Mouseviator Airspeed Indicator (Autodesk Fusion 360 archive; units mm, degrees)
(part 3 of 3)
sketch "Sketch2" plane through (-9, 0, 0) normal (-1, 0, 0) x axis (0, 0, 1)
  line L1 (17.6759, -7.8551) -> (17.6759, -8.2743)
  line L2 (17.6759, 6.5541) -> (17.6759, 6.1349)
  line L3 (15.1488, 7.9637) -> (16.0708, 8.8862)
  line L4 (13.2614, 9.6883) -> (14.9498, 8.0007)
  line L5 (14.1646, 10.7942) -> (13.274, 9.873)
  line L6 (11.3861, 12.4172) -> (11.8062, 12.4172)
  line L7 (-2.9837, 12.4223) -> (-2.5631, 12.4223)
  line L8 (-8.873, 6.1148) -> (-8.873, 6.5351)
  line L9 (-8.873, -8.2553) -> (-8.873, -7.835)
  line L10 (-2.5727, -14.1374) -> (-2.9927, -14.1374)
  line L11 (11.8062, -14.1374) -> (11.3861, -14.1374)
  circle C1 centre (4.4067, -14.3661) radius 0.9326
  circle C2 centre (4.4067, 12.6425) radius 0.9209
  arc A1 centre (20.4506, -5.5922) radius 9.3615 clockwise from (14.1561, -12.5216) to (13.2578, -11.584)
  arc A2 centre (13.4029, -11.5164) radius 0.16 clockwise from (13.2578, -11.584) to (13.2817, -11.4119)
  arc A3 centre (46.5076, -42.5964) radius 45.5679 clockwise from (13.2817, -11.4119) to (14.9454, -9.7291)
  arc A4 centre (15.0489, -9.8031) radius 0.1272 clockwise from (14.9454, -9.7291) to (15.1488, -9.7243)
  arc A5 centre (5.0124, -21.2003) radius 15.3116 clockwise from (15.1488, -9.7243) to (16.0692, -10.6082)
  arc A6 centre (4.4067, -0.8601) radius 15.2 clockwise from (17.6759, -8.2743) to (16.0692, -10.6082)
  arc A7 centre (4.4067, -0.8601) radius 15 clockwise from (17.6759, 6.1349) to (17.6759, -7.8551)
  arc A8 centre (4.4067, -0.8601) radius 15.2 clockwise from (16.0708, 8.8862) to (17.6759, 6.5541)
  arc A9 centre (15.0762, 8.1271) radius 0.1788 clockwise from (15.1488, 7.9637) to (14.9498, 8.0007)
  arc A10 centre (13.3772, 9.7732) radius 0.1436 clockwise from (13.2614, 9.6883) to (13.274, 9.873)
  arc A11 centre (4.4067, -0.8601) radius 15.2 clockwise from (11.8062, 12.4172) to (14.1646, 10.7942)
  arc A12 centre (4.4067, -0.8601) radius 15 clockwise from (6.3118, 14.0184) to (11.3861, 12.4172)
  arc A13 centre (4.4067, 12.6425) radius 2.35 clockwise from (2.5017, 14.0184) to (6.3118, 14.0184)
  arc A14 centre (4.4067, -0.8601) radius 15 clockwise from (-2.5631, 12.4223) to (2.5017, 14.0184)
  arc A15 centre (4.4067, -0.8601) radius 15.2 clockwise from (-5.3368, 10.8063) to (-2.9837, 12.4223)
  arc A16 centre (-27.3451, -12.2651) radius 31.885 clockwise from (-5.3368, 10.8063) to (-4.4145, 9.8899)
  arc A17 centre (-4.4478, 9.7984) radius 0.0973 clockwise from (-4.4145, 9.8899) to (-4.4326, 9.7023)
  arc A18 centre (158.4507, -154.9056) radius 231.5744 clockwise from (-6.1572, 7.9777) to (-4.4326, 9.7023)
  arc A19 centre (-6.2246, 8.0786) radius 0.1214 clockwise from (-6.1572, 7.9777) to (-6.3071, 7.9895)
  arc A20 centre (0.3735, 15.8934) radius 10.349 clockwise from (-6.3071, 7.9895) to (-7.2502, 8.8947)
  arc A21 centre (4.4067, -0.8601) radius 15.2 clockwise from (-8.873, 6.5351) to (-7.2502, 8.8947)
  arc A22 centre (4.4067, -0.8601) radius 15 clockwise from (-8.873, -7.835) to (-8.873, 6.1148)
  arc A23 centre (4.4067, -0.8601) radius 15.2 clockwise from (-7.2537, -10.6107) to (-8.873, -8.2553)
  arc A24 centre (39.755, -59.3372) radius 67.706 clockwise from (-7.2537, -10.6107) to (-6.3203, -9.7271)
  arc A25 centre (-6.2457, -9.8075) radius 0.1097 clockwise from (-6.3203, -9.7271) to (-6.1786, -9.7208)
  arc A26 centre (-37.8756, -43.7201) radius 46.4828 clockwise from (-6.1786, -9.7208) to (-4.4513, -11.4172)
  arc A27 centre (-4.5901, -11.5514) radius 0.193 clockwise from (-4.4513, -11.4172) to (-4.4051, -11.6064)
  arc A28 centre (-93.0217, 77.7849) radius 125.8718 clockwise from (-4.4051, -11.6064) to (-5.3401, -12.5237)
  arc A29 centre (4.4067, -0.8601) radius 15.2 clockwise from (-2.9927, -14.1374) to (-5.3401, -12.5237)
  arc A30 centre (4.4067, -0.8601) radius 15 clockwise from (2.4989, -15.7383) to (-2.5727, -14.1374)
  arc A31 centre (4.4067, -14.3661) radius 2.35 clockwise from (6.3145, -15.7383) to (2.4989, -15.7383)
  arc A32 centre (4.4067, -0.8601) radius 15 clockwise from (11.3861, -14.1374) to (6.3145, -15.7383)
  arc A33 centre (4.4067, -0.8601) radius 15.2 clockwise from (14.1561, -12.5216) to (11.8062, -14.1374)
  arc A34 centre (-26.4034, -0.8798) radius 26.136 clockwise from (-1.0345, 5.4058) to (-1.0377, -7.1782)
  arc A35 centre (-0.1196, 5.6325) radius 0.9426 clockwise from (-1.0345, 5.4058) to (-0.0026, 6.5678)
  arc A36 centre (4.422, 47.5969) radius 41.267 clockwise from (8.8766, 6.5711) to (-0.0026, 6.5678)
  arc A37 centre (8.9782, 5.6352) radius 0.9413 clockwise from (8.8766, 6.5711) to (9.8912, 5.4058)
  arc A38 centre (34.9402, -0.888) radius 25.8276 clockwise from (9.8883, -7.1704) to (9.8912, 5.4058)
  arc A39 centre (8.9696, -7.4008) radius 0.9472 clockwise from (9.8883, -7.1704) to (8.8766, -8.3434)
  arc A40 centre (4.4407, -53.3263) radius 45.2011 clockwise from (-0.0175, -8.3456) to (8.8766, -8.3434)
  arc A41 centre (-0.1204, -7.406) radius 0.9452 clockwise from (-0.0175, -8.3456) to (-1.0377, -7.1782)
  arc A42 centre (-26.528, -0.9077) radius 24.6493 clockwise from (-3.0078, 6.467) to (-2.997, -8.248)
  arc A43 centre (-3.9071, 6.2045) radius 0.9369 clockwise from (-3.7182, 7.1221) to (-3.0078, 6.467)
  arc A44 centre (6.7761, 58.1143) radius 52.0609 clockwise from (-3.7182, 7.1221) to (-4.7329, 7.3415)
  arc A45 centre (-4.5799, 8.1251) radius 0.7984 clockwise from (-4.7329, 7.3415) to (-4.4077, 8.9046)
  arc A46 centre (4.4829, 51.1212) radius 43.1426 clockwise from (12.6671, 8.762) to (-4.4077, 8.9046)
  arc A47 centre (4.7913, 50.3763) radius 43.9488 clockwise from (13.0119, 7.2031) to (12.5964, 7.1261)
  arc A48 centre (12.7605, 6.2172) radius 0.9236 clockwise from (11.8575, 6.4115) to (12.5964, 7.1261)
  arc A49 centre (34.8824, -0.9362) radius 24.1688 clockwise from (11.8459, -8.2474) to (11.8575, 6.4115)
  arc A50 centre (12.7102, -7.9921) radius 0.9012 clockwise from (12.5964, -8.8861) to (11.8459, -8.2474)
  arc A51 centre (11.8848, -14.4786) radius 5.6376 clockwise from (12.5964, -8.8861) to (13.6034, -9.1093)
  arc A52 centre (13.4359, -9.8881) radius 0.7966 clockwise from (13.6034, -9.1093) to (13.2657, -10.6663)
  arc A53 centre (4.447, -50.9752) radius 41.2623 clockwise from (-4.387, -10.6697) to (13.2657, -10.6663)
  arc A54 centre (-4.5581, -9.8892) radius 0.799 clockwise from (-4.387, -10.6697) to (-4.723, -9.1073)
  arc A55 centre (-3.467, -12.5196) radius 3.6361 clockwise from (-4.723, -9.1073) to (-3.7296, -8.893)
  arc A56 centre (-3.7878, -8.0884) radius 0.8068 clockwise from (-2.997, -8.248) to (-3.7296, -8.893)
  circle C3 centre (13.4276, 8.1127) radius 1
  circle C4 centre (13.4276, 8.1127) radius 0.6875
  circle C5 centre (4.4067, 12.6425) radius 2.25
  circle C6 centre (4.4067, -14.3661) radius 2.25
  circle C7 centre (4.4067, -14.3661) radius 1.25
  circle C8 centre (4.4067, 12.6425) radius 1.25
  circle C9 centre (0.6086, 10.5315) radius 1.5
  circle C10 centre (0.6086, 10.5315) radius 0.9
  circle C11 centre (8.2306, 10.5315) radius 1.5
  circle C12 centre (8.2306, 10.5315) radius 0.9
  circle C13 centre (0.6086, -12.3285) radius 1.5
  circle C14 centre (0.6086, -12.3285) radius 0.9
  circle C15 centre (8.2306, -12.3285) radius 1.5
  circle C16 centre (8.2306, -12.3285) radius 0.9
  circle C17 centre (-8.0934, -5.8938) radius 0.75
  circle C18 centre (16.9066, -5.8938) radius 0.75
  circle C19 centre (-8.0934, 4.1062) radius 0.75
  circle C20 centre (16.9066, 4.1062) radius 0.75
  circle C21 centre (-8.0934, -5.8938) radius 0.25
  circle C22 centre (16.9066, -5.8938) radius 0.25
  circle C23 centre (-8.0934, 4.1062) radius 0.25
  circle C24 centre (16.9066, 4.1062) radius 0.25
  circle C25 centre (-5.5763, -0.8796) radius 2
  circle C26 centre (-5.5763, -0.8796) radius 1.5
  circle C27 centre (0.6086, 10.5315) radius 0.25
  circle C28 centre (8.2286, 10.5315) radius 0.25
  circle C29 centre (0.6086, -12.3285) radius 0.25
  circle C30 centre (8.2286, -12.3285) radius 0.25
  point P113 (13.0119, 7.2031)
  point P114 (12.6671, 8.762)
  tangent A34 A35
  tangent A36 A37
  tangent A37 A38
  tangent A38 A39
  tangent A39 A40
  tangent A34 A41
  tangent A43 A44
  tangent A46 A47
  tangent A47 A48
  tangent A50 A51
  tangent A52 A53
  tangent A53 A54
  tangent A55 A56
  concentric C3 C4
  coincident C3 P113
  coincident C3 P114
  concentric C2 C5
  concentric C1 C6
  concentric C6 C7
  concentric C5 C8
  concentric C9 C10
  concentric C17 C21
  concentric C25 C26
  concentric C10 C27
  dimension "d41" diameter C3 = 2
  dimension "d42" diameter C4 = 1.375
  dimension "d47" diameter C5 = 4.5
  dimension "d48" diameter C6 = 4.5
  dimension "d49" diameter C7 = 2.5
  dimension "d50" diameter C8 = 2.5
  dimension "d51" diameter C9 = 3
  dimension "d52" diameter C10 = 1.8
  dimension "d57" diameter C17 = 1.5
  dimension "d62" diameter C21 = 0.5
  dimension "d67" diameter C25 = 4
  dimension "d68" diameter C26 = 3
  dimension "d73" diameter C27 = 0.5
  dimension "d55" R-Pattern1-uDistance = 7.622
  dimension "d56" R-Pattern1-vDistance = -22.86
  dimension "d60" R-Pattern2-uDistance = 25
  dimension "d61" R-Pattern2-vDistance = 10
  dimension "d65" R-Pattern3-uDistance = 25
  dimension "d66" R-Pattern3-vDistance = 10
  dimension "d76" R-Pattern4-uDistance = 7.62
  dimension "d77" R-Pattern4-vDistance = -22.86
extrude "Extrude12" add sketch "Sketch2" profile of A34 A35 A36 A37 A38 A39 A40 A41 A42 A43 A44 A45 A46 A47 A48 A49 A50 A51 A52 A53 A54 A55 A56 C3 along normal blind 0.3
extrude "Extrude13" add sketch "Sketch2" profile of L4 C3 C4 along normal blind 4.7
extrude "Extrude14" add sketch "Sketch2" profile of C25 C26 along normal blind 4.4
extrude "Extrude15" add sketch "Sketch2" profile of C17 C18 C19 C20 C21 C22 C23 C24 along normal blind 0.3
extrude "Extrude16" add sketch "Sketch2" profile of C9 C10 C11 C12 C13 C14 C15 C16 along normal blind 0.3
extrude "Extrude17" new body sketch "Sketch2" profile of C27 C28 C29 C30 along normal blind 4
fillet "Fillet1" radius 0.3
chamfer "Chamfer2" distance 0.4
sketch "Sketch3" plane through (0, 0, 0) normal (1, 0, 0) x axis (0, 0, -1)
  line L1 (-29.7964, 19.8845) -> (16.7624, 19.8845)
  line L2 (-29.7964, -21.2182) -> (-29.7964, 19.8845)
  line L3 (16.7624, -21.2182) -> (-29.7964, -21.2182)
  line L4 (16.7624, 19.8845) -> (16.7624, -21.2182)
  horizontal L1
  vertical L2
  horizontal L3
  vertical L4
extrude "Extrude18" new body sketch "Sketch3" against normal blind 0.01
move "Move1"
split "Split1" bodies "Body_Top (1)"
move "Move2"
named bodies: "Body_Top", "Needle", "Body_Top (1)"

design "Instrument Bezel and Glass MS33638C"
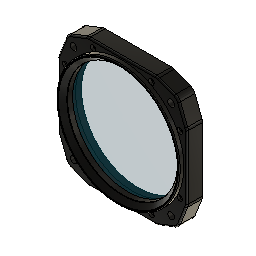
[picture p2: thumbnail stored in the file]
canvas "Canvas4"
canvas "Canvas1"
sketch "Instrument Sketch" plane through (0, 0, 0) normal (1, 0, 0) x axis (0, 1, 0)
  line L1 (-41.4655, 20.5361) -> (-41.4655, 0)
  line L2 (-36.4994, 34.1766) -> (-41.1157, 22.3885)
  line L3 (-23.2139, 41.1177) -> (-33.6166, 37.0564)
  line L4 (0, 41.4655) -> (-21.3665, 41.4655)
  line L5 (0, 22.5) -> (0, 0)
  line L6 (0, 0) -> (0, 41.4655)
  line L7 (-41.4655, 0) -> (0, 0)
  line L8 (41.4655, 20.5361) -> (41.4655, 0)
  line L9 (36.4994, 34.1766) -> (41.1157, 22.3885)
  line L10 (23.2139, 41.1177) -> (33.6166, 37.0564)
  line L11 (0, 41.4655) -> (21.3665, 41.4655)
  line L12 (-41.4655, -20.5361) -> (-41.4655, 0)
  line L13 (-36.4994, -34.1766) -> (-41.1157, -22.3885)
  line L14 (-23.2139, -41.1177) -> (-33.6166, -37.0564)
  line L15 (0, -41.4655) -> (-21.3665, -41.4655)
  line L16 (41.4655, -20.5361) -> (41.4655, 0)
  line L17 (36.4994, -34.1766) -> (41.1157, -22.3885)
  line L18 (0, -41.4655) -> (21.3665, -41.4655)
  line L19 (23.2139, -41.1177) -> (33.6166, -37.0564)
  line L20 (-1.0967, 0) -> (0, 0)
  line L21 (-72.2485, 72.2485) -> (0, 0)
  circle C1 centre (0, 0) radius 39.6875
  circle C2 centre (31.4309, 31.4309) radius 2.159
  circle C3 centre (-31.4309, -31.4309) radius 2.159
  circle C4 centre (-31.4309, 31.4309) radius 2.159
  circle C5 centre (31.4309, -31.4309) radius 2.159
  arc A1 centre (-31.7692, 32.3242) radius 5.08 clockwise from (-36.4994, 34.1766) to (-33.6166, 37.0564)
  arc A2 centre (-21.3665, 36.3855) radius 5.08 clockwise from (-23.2139, 41.1177) to (-21.3665, 41.4655)
  arc A3 centre (-36.3855, 20.5361) radius 5.08 clockwise from (-41.4655, 20.5361) to (-41.1157, 22.3885)
  arc A4 centre (36.3855, 20.5361) radius 5.08 clockwise from (41.1157, 22.3885) to (41.4655, 20.5361)
  arc A5 centre (31.7692, 32.3242) radius 5.08 clockwise from (33.6166, 37.0564) to (36.4994, 34.1766)
  arc A6 centre (21.3665, 36.3855) radius 5.08 clockwise from (21.3665, 41.4655) to (23.2139, 41.1177)
  arc A7 centre (-36.3855, -20.5361) radius 5.08 clockwise from (-41.1157, -22.3885) to (-41.4655, -20.5361)
  arc A8 centre (-31.7692, -32.3242) radius 5.08 clockwise from (-33.6166, -37.0564) to (-36.4994, -34.1766)
  arc A9 centre (-21.3665, -36.3855) radius 5.08 clockwise from (-21.3665, -41.4655) to (-23.2139, -41.1177)
  arc A10 centre (36.3855, -20.5361) radius 5.08 clockwise from (41.4655, -20.5361) to (41.1157, -22.3885)
  arc A11 centre (31.7692, -32.3242) radius 5.08 clockwise from (36.4994, -34.1766) to (33.6166, -37.0564)
  arc A12 centre (21.3665, -36.3855) radius 5.08 clockwise from (23.2139, -41.1177) to (21.3665, -41.4655)
  circle C6 centre (0, 0) radius 35.5256
  point P1 (0, 0)
  point P2 (0, 0)
  point P13 (0, 0)
  point P3 (-41.4655, 0)
  point P23 (41.4655, 0)
  point P4 (0, 41.4655)
  point P33 (0, 41.4655)
  point P14 (-36.4994, 34.1766)
  point P27 (36.4994, 34.1766)
  point P15 (-33.6166, 37.0564)
  point P29 (33.6166, 37.0564)
  point P17 (-23.2139, 41.1177)
  point P30 (23.2139, 41.1177)
  point P18 (-21.3665, 41.4655)
  point P32 (21.3665, 41.4655)
  point P20 (-41.4655, 20.5361)
  point P24 (41.4655, 20.5361)
  point P21 (-41.1157, 22.3885)
  point P26 (41.1157, 22.3885)
  point P34 (-41.4655, 0)
  point P44 (0, -41.4655)
  point P38 (-36.4994, -34.1766)
  point P40 (-33.6166, -37.0564)
  point P41 (-23.2139, -41.1177)
  point P43 (-21.3665, -41.4655)
  point P35 (-41.4655, -20.5361)
  point P37 (-41.1157, -22.3885)
  point P45 (41.4655, 0)
  point P46 (41.4655, -20.5361)
  point P48 (41.1157, -22.3885)
  point P49 (36.4994, -34.1766)
  point P51 (33.6166, -37.0564)
  point P53 (23.2139, -41.1177)
  point P54 (21.3665, -41.4655)
  point P55 (0, -41.4655)
  point P57 (0, 0)
  point P58 (-1.0967, 0)
  point P56 (0, 0)
  point P59 (0, 0)
  point P6 (0, 0)
  coincident P1 P2
  vertical L1
  horizontal L4
  equal C3 C4
  equal C3 C5
  equal C2 C5
  coincident P1 P13
  perpendicular L1 L7
  tangent L2 A1
  tangent L3 A1
  tangent L3 A2
  tangent L4 A2
  equal A1 A2
  tangent L1 A3
  tangent L2 A3
  equal A1 A3
  symmetric P3 L6 P23
  symmetric P4 L6 P33
  symmetric L6 P14 P27
  symmetric L6 P15 P29
  symmetric L6 A1 A5
  symmetric L6 P17 P30
  symmetric L6 P18 P32
  symmetric L6 A2 A6
  symmetric L6 P20 P24
  symmetric L6 P21 P26
  symmetric L6 A3 A4
  symmetric P3 L7 P34
  symmetric P4 L7 P44
  symmetric L7 P14 P38
  symmetric L7 P15 P40
  symmetric L7 A1 A8
  symmetric L7 P17 P41
  symmetric L7 P18 P43
  symmetric L7 A2 A9
  symmetric L7 P20 P35
  symmetric L7 P21 P37
  symmetric L7 A3 A7
  symmetric L7 P23 P45
  symmetric L7 P24 P46
  symmetric L7 P26 P48
  symmetric L7 A4 A10
  symmetric L7 P27 P49
  symmetric L7 P29 P51
  symmetric L7 A5 A11
  symmetric L7 P30 P53
  symmetric L7 P32 P54
  symmetric L7 A6 A12
  symmetric L7 P33 P55
  coincident P23 P45
  coincident P1 P57
  coincident L7 P58
  perpendicular L6 L20
  coincident P56 P59
  coincident P6 P56
  dimension "d1" diameter C1 = 79.375 (= "3 1/8")
  dimension "d2" radius A1 = 5.08 (= "0.20")
  dimension "d10" = 82.931 (= "3.265")
  dimension "d11" = 82.931 (= "d10")
  dimension "d13" angle L6 L21 = 45 (= "Angular Dimension-2")
extrude "Extrude1" new body sketch "Instrument Sketch" profile of C1 L1 L2 L3 L4 C2 C3 C4 C5 A1 A2 A3 L8 A4 L9 A5 L10 A6 L11 L12 A7 L13 A8 L14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 along normal blind 10.25
extrude "Extrude2" sketch "Instrument Sketch" profile of C1 C6 blind 3
chamfer "Chamfer1" distance 3
canvas "Canvas2"
canvas "Canvas3"
move "Move1"
fillet "Fillet1" radius 0.5 0.5969 (= "0.047   * 0.5")
fillet "Fillet2" radius 1
sketch "Sketch2" plane through (0, 2, 0) normal (0, 1, 0) x axis (-1, 0, 0)
  line L1 (-36.4994, -34.1766) -> (-41.1157, -22.3885)
  line L2 (-23.2139, -41.1177) -> (-33.6166, -37.0564)
  line L3 (21.3665, -41.4655) -> (-21.3665, -41.4655)
  line L4 (33.6166, -37.0564) -> (23.2139, -41.1177)
  line L5 (41.1157, -22.3885) -> (36.4994, -34.1766)
  line L6 (41.4655, 20.5361) -> (41.4655, -20.5361)
  line L7 (36.4994, 34.1766) -> (41.1157, 22.3885)
  line L8 (23.2139, 41.1177) -> (33.6166, 37.0564)
  line L9 (-21.3665, 41.4655) -> (21.3665, 41.4655)
  line L10 (-33.6166, 37.0564) -> (-23.2139, 41.1177)
  line L11 (-41.1157, 22.3885) -> (-36.4994, 34.1766)
  line L12 (-41.4655, -20.5361) -> (-41.4655, 20.5361)
  line L13 (0, 40.9) -> (-3.1855, 35.3825)
  line L14 (3.1855, 35.3825) -> (0, 40.9)
  line L15 (0, 32.0284) -> (0, 40.9)
  line L16 (3.1855, 35.3825) -> (-3.1855, 35.3825)
  circle C1 centre (-31.4309, -31.4309) radius 2.159
  circle C2 centre (31.4309, 31.4309) radius 2.159
  circle C3 centre (31.4309, -31.4309) radius 2.159
  circle C4 centre (-31.4309, 31.4309) radius 2.159
  circle C5 centre (0, 0) radius 35.5256
  arc A1 centre (-36.3855, -20.5361) radius 5.08 clockwise from (-41.1157, -22.3885) to (-41.4655, -20.5361)
  arc A2 centre (-31.7692, -32.3242) radius 5.08 clockwise from (-33.6166, -37.0564) to (-36.4994, -34.1766)
  arc A3 centre (-21.3665, -36.3855) radius 5.08 clockwise from (-21.3665, -41.4655) to (-23.2139, -41.1177)
  arc A4 centre (21.3665, -36.3855) radius 5.08 clockwise from (23.2139, -41.1177) to (21.3665, -41.4655)
  arc A5 centre (31.7692, -32.3242) radius 5.08 clockwise from (36.4994, -34.1766) to (33.6166, -37.0564)
  arc A6 centre (36.3855, -20.5361) radius 5.08 clockwise from (41.4655, -20.5361) to (41.1157, -22.3885)
  arc A7 centre (36.3855, 20.5361) radius 5.08 clockwise from (41.1157, 22.3885) to (41.4655, 20.5361)
  arc A8 centre (31.7692, 32.3242) radius 5.08 clockwise from (33.6166, 37.0564) to (36.4994, 34.1766)
  arc A9 centre (21.3665, 36.3855) radius 5.08 clockwise from (21.3665, 41.4655) to (23.2139, 41.1177)
  arc A10 centre (-21.3665, 36.3855) radius 5.08 clockwise from (-23.2139, 41.1177) to (-21.3665, 41.4655)
  arc A11 centre (-31.7692, 32.3242) radius 5.08 clockwise from (-36.4994, 34.1766) to (-33.6166, 37.0564)
  arc A12 centre (-36.3855, 20.5361) radius 5.08 clockwise from (-41.4655, 20.5361) to (-41.1157, 22.3885)
  circle C6 centre (0, 0) radius 39.65
  point P1 (0, 0)
  point P43 (0, 0)
  point P44 (-3.1855, 35.3825)
  point P47 (0, 32.0284)
  point P46 (3.1855, 35.3825)
  point P48 (0, 35.3825)
  point P49 (0, 39.65)
  point P45 (0, 40.9)
  coincident P1 P43
  coincident C5 P44
  vertical L15
  vertical P43 P47
  coincident C5 P46
  midpoint L16 P48
  coincident L15 P48
  coincident C6 P49
  coincident L15 P49
  dimension "d19" diameter C6 = 79.3
  dimension "d45" angle L13 L14 = 60 (= "Angular Dimension-2")
  dimension "d47" distance P45 P49 = 1.25
extrude "Extrude3" cut sketch "Sketch2" profile of C5 C6 L13 L14 to an object offset -6.5
place_component sketch "Sketch1"
sketch "Sketch1" plane through (0, -4.75, 0) normal (0, 1, 0) x axis (-1, 0, 0)
  line L1 (0, 40.9) -> (0.7255, 39.6434)
  line L2 (-0.7255, 39.6434) -> (0, 40.9)
  line L3 (0, 40.6) -> (0.6381, 39.4948)
  line L4 (-0.6381, 39.4948) -> (0, 40.6)
  circle C1 centre (0, 0) radius 35.5256
  circle C2 centre (0, 0) radius 39.55
  arc A1 centre (0, 0) radius 39.65 clockwise from (0.7255, 39.6434) to (-0.7255, 39.6434)
  arc A2 centre (0, 0) radius 39.5 clockwise from (0.6381, 39.4948) to (-0.6381, 39.4948)
  point P1 (0, 0)
  point P3 (0, 0)
  coincident P1 P3
  dimension "d48" = -0.15
extrude "Extrude1" new body sketch "Sketch1" profile of C1 C2 L3 L4 A2 along normal blind 3
sketch "Sketch1" plane through (0, -1.75, 0) normal (0, 1, 0) x axis (-1, 0, 0)
  line L1 (0, 40.9) -> (-0.7255, 39.6434)
  line L2 (0.7255, 39.6434) -> (0, 40.9)
  line L3 (0, 40.6) -> (-0.5956, 39.5684)
  line L4 (0.5956, 39.5684) -> (0, 40.6)
  line L5 (-0.7521, 39.2974) -> (-0.5956, 39.5684)
  line L6 (0.7129, 39.3653) -> (0.5956, 39.5684)
  line L7 (-0.6089, 39.5453) -> (0, 40.6)
  line L8 (0, 40.6) -> (0.6089, 39.5453)
  circle C1 centre (0, 0) radius 39.65
  circle C2 centre (0, 0) radius 36.65
  arc A1 centre (0, 0) radius 39.55 clockwise from (0.6089, 39.5453) to (-0.6089, 39.5453)
  parallel L4 L6
  collinear L3 L5
  dimension "d25" diameter C1 = 79.3
  dimension "d29" = -3
  dimension "d49" = 0.15
extrude "Extrude1" new body sketch "Sketch1" profile of L7 C1 C2 L3 L4 L5 L6 to an object bodies "Bezel Seal"
sketch "Panel Sketch" plane through (0, -8.25, 0) normal (0, -1, 0) x axis (1, 0, 0)
  line L1 (-40.1846, 22.0238) -> (-35.5682, 33.812)
  line L2 (-40.4655, -20.5361) -> (-40.4655, 20.5361)
  line L3 (-35.5682, -33.812) -> (-40.1846, -22.0238)
  line L4 (-22.8502, -40.1861) -> (-33.2529, -36.1249)
  line L5 (21.3665, -40.4655) -> (-21.3665, -40.4655)
  line L6 (33.2529, -36.1249) -> (22.8502, -40.1861)
  line L7 (40.1846, -22.0238) -> (35.5682, -33.812)
  line L8 (40.4655, 20.5361) -> (40.4655, -20.5361)
  line L9 (35.5682, 33.812) -> (40.1846, 22.0238)
  line L10 (22.8502, 40.1861) -> (33.2529, 36.1249)
  line L11 (-21.3665, 40.4655) -> (21.3665, 40.4655)
  line L12 (-33.2529, 36.1249) -> (-22.8502, 40.1861)
  circle C1 centre (31.4309, 31.4309) radius 2.159
  circle C2 centre (-31.4309, -31.4309) radius 2.159
  circle C3 centre (-31.4309, 31.4309) radius 2.159
  circle C4 centre (31.4309, -31.4309) radius 2.159
  circle C5 centre (0, 0) radius 39.6875
  arc A1 centre (-36.3855, 20.5361) radius 4.08 clockwise from (-40.4655, 20.5361) to (-40.1846, 22.0238)
  arc A2 centre (-36.3855, -20.5361) radius 4.08 clockwise from (-40.1846, -22.0238) to (-40.4655, -20.5361)
  arc A3 centre (-31.7692, -32.3242) radius 4.08 clockwise from (-33.2529, -36.1249) to (-35.5682, -33.812)
  arc A4 centre (-21.3665, -36.3855) radius 4.08 clockwise from (-21.3665, -40.4655) to (-22.8502, -40.1861)
  arc A5 centre (21.3665, -36.3855) radius 4.08 clockwise from (22.8502, -40.1861) to (21.3665, -40.4655)
  arc A6 centre (31.7692, -32.3242) radius 4.08 clockwise from (35.5682, -33.812) to (33.2529, -36.1249)
  arc A7 centre (36.3855, -20.5361) radius 4.08 clockwise from (40.4655, -20.5361) to (40.1846, -22.0238)
  arc A8 centre (36.3855, 20.5361) radius 4.08 clockwise from (40.1846, 22.0238) to (40.4655, 20.5361)
  arc A9 centre (31.7692, 32.3242) radius 4.08 clockwise from (33.2529, 36.1249) to (35.5682, 33.812)
  arc A10 centre (21.3665, 36.3855) radius 4.08 clockwise from (21.3665, 40.4655) to (22.8502, 40.1861)
  arc A11 centre (-21.3665, 36.3855) radius 4.08 clockwise from (-22.8502, 40.1861) to (-21.3665, 40.4655)
  arc A12 centre (-31.7692, 32.3242) radius 4.08 clockwise from (-35.5682, 33.812) to (-33.2529, 36.1249)
sketch "Clamping Holes" plane through (0, -8.25, 0) normal (0, -1, 0) x axis (1, 0, 0)
  line L1 (0, 17.2297) -> (0, 0)
  line L2 (-22.2137, 0) -> (0, 0)
  circle C1 centre (-36.96, 18.76) radius 1
  circle C2 centre (36.96, 18.76) radius 1
  circle C3 centre (-36.96, -18.76) radius 1
  circle C4 centre (36.96, -18.76) radius 1
  circle C5 centre (-18.76, 36.96) radius 1
  circle C6 centre (18.76, 36.96) radius 1
  circle C7 centre (18.76, -36.96) radius 1
  circle C8 centre (-18.76, -36.96) radius 1
  point P1 (0, 0)
  point P3 (0, 0)
  point P5 (0, 0)
  point P2 (-36.96, 18.76)
  point P10 (-18.76, 36.96)
  coincident P1 P3
  vertical L1
  coincident P1 P5
  perpendicular L1 L2
  symmetric C1 L1 C2
  symmetric C1 L2 C3
  symmetric L2 C2 C4
  symmetric L1 C5 C6
  symmetric L2 C5 C8
  symmetric L2 C6 C7
  dimension "d32" diameter C1 = 2
  dimension "d33" distance P1 P2 = 18.76 (= "( 37.52 / 2 ) * 1 mm")
  dimension "d34" distance P1 P2 = 36.96 (= "( 73.92 / 2 ) * 1 mm")
  dimension "d37" diameter C5 = 2 (= "d32")
  dimension "d38" distance P1 P10 = 36.96 (= "d34")
  dimension "d39" distance P1 P10 = 18.76 (= "d33")
hole "Hole1" HoleDepth 10.25 HoleDiameter 1.8 CBDepth 1.6 CBDiameter 3.5
component_from_bodies "Body->Comp"
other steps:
base_feature "Base Feature" bodies "Standard Bezel"
create_component "CreateComponent1" sketch "Sketch1"
create_component "CreateComponent2"
create_component "CreateComponent4"
remove_body "RemoveBody1"
named bodies: "Bezel Seal", "Standard Bezel"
